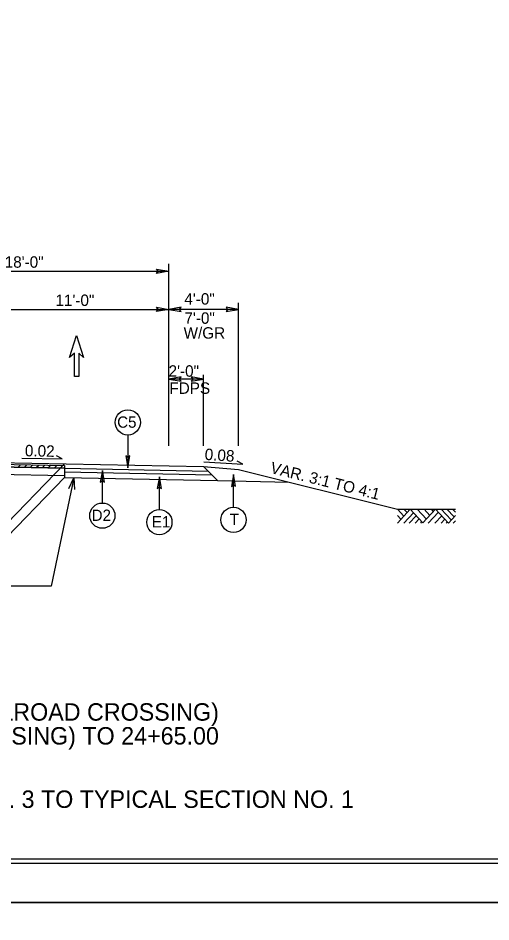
# Model space of a CAD drawing. Extents: x 1901718 to 1902220, y 193828 to 194187.
# Drawn here: x 1902060 to 1902087.2, y 193936.9 to 193988.8 of the extents above; entities that cross this region are included whole.
import ezdxf

# ---------------------------------------------------------------- set-up
doc = ezdxf.new("R2010")
doc.units = 0
for name, color, linetype in [('Old_Level_1', 7, 'Continuous'), ('Old_Level_11', 7, 'Continuous'), ('Old_Level_2', 7, 'Continuous'), ('Old_Level_20', 7, 'Continuous'), ('Prop Dimension', 7, 'Continuous'), ('Prop Dimension Text', 7, 'Continuous'), ('Sheet Border Standard 30in CELL', 7, 'Continuous'), ('Sheet Cutting Line CELL', 7, 'Continuous'), ('Sheet Plot Border Inside CELL', 7, 'Continuous'), ('Sheet Plot Border Outside CELL', 7, 'Continuous'), ('Typical Terminator CELL', 7, 'Continuous')]:
    doc.layers.add(name, color=color, linetype=linetype)

# ---------------------------------------------------------------- blocks, each defined once
blk = doc.blocks.new('TERMINATOR')
at = {"layer": 'Typical Terminator CELL'}
blk.add_lwpolyline([(-0.469, 0.081), (0, 0), (-0.471, -0.083), (-0.411, 0)], close=True, dxfattribs=at)

msp = doc.modelspace()

# ---------------------------------------------------------------- linework, layer by layer
at = {"layer": 'Old_Level_1'}
for p, q in [((1902062.559, 193963.461), (1902062.237, 193963.648)), ((1902050.692, 193963.426), (1902070.692, 193963.026)), ((1902050.692, 193963.322), (1902062.692, 193963.082)), ((1902050.692, 193963.176), (1902062.692, 193962.936)), ((1902062.692, 193962.936), (1902050.692, 193963.176)), ((1902062.692, 193963.186), (1902058.216, 193958.562)), ((1902060.039, 193962.989), (1902060.182, 193963.132)), ((1902060.255, 193963.51), (1902062.559, 193963.461)), ((1902060.386, 193962.982), (1902060.529, 193963.125)), ((1902060.733, 193962.975), (1902060.876, 193963.118)), ((1902061.079, 193962.968), (1902061.222, 193963.112)), ((1902061.426, 193962.961), (1902061.569, 193963.105)), ((1902061.772, 193962.955), (1902061.916, 193963.098)), ((1902062.119, 193962.948), (1902062.262, 193963.091)), ((1902062.466, 193962.941), (1902062.609, 193963.084)), ((1902062.692, 193963.082), (1902062.692, 193962.394)), ((1902070.705, 193963.302), (1902072.94, 193963.156)), ((1902072.94, 193963.156), (1902072.618, 193963.343)), ((1902050.692, 193962.76), (1902062.692, 193962.52)), ((1902062.692, 193962.936), (1902070.948, 193962.771)), ((1902062.692, 193962.728), (1902071.16, 193962.558)), ((1902070.692, 193963.026), (1902072.692, 193962.866)), ((1902070.692, 193963.026), (1902071.5, 193962.218)), ((1902072.692, 193962.866), (1902081.827, 193960.583)), ((1902062.692, 193962.394), (1902058.216, 193957.77)), ((1902062.692, 193962.394), (1902071.5, 193962.218)), ((1902071.5, 193962.218), (1902075.613, 193962.136)), ((1902081.827, 193960.583), (1902082.202, 193960.18)), ((1902081.827, 193959.778), (1902082.569, 193960.575)), ((1902082.202, 193960.583), (1902082.389, 193960.382)), ((1902082.569, 193960.575), (1902083.293, 193959.796)), ((1902082.96, 193960.583), (1902083.493, 193960.01)), ((1902083.293, 193959.796), (1902084.024, 193960.582)), ((1902083.358, 193960.583), (1902083.691, 193960.224)), ((1902083.76, 193960.583), (1902083.893, 193960.44)), ((1902084.024, 193960.582), (1902084.765, 193959.786)), ((1902084.346, 193960.583), (1902084.926, 193959.96)), ((1902084.679, 193960.583), (1902085.093, 193960.139)), ((1902084.999, 193960.583), (1902085.169, 193960.4)), ((1902081.827, 193960.221), (1902082.033, 193959.999)), ((1902082.201, 193959.778), (1902082.755, 193960.374)), ((1902082.51, 193959.778), (1902082.911, 193960.207)), ((1902082.857, 193959.778), (1902083.084, 193960.021)), ((1902083.603, 193959.778), (1902084.189, 193960.406)), ((1902083.973, 193959.778), (1902084.373, 193960.207)), ((1902084.339, 193959.778), (1902084.556, 193960.011)), ((1902084.765, 193959.786), (1902085.169, 193960.221)), ((1902083.168, 193959.778), (1902083.239, 193959.854)), ((1902084.634, 193959.778), (1902084.703, 193959.852)), ((1902085.035, 193959.778), (1902085.169, 193959.921))]:
    msp.add_line(p, q, dxfattribs=at)
for points in [[(1902063.24, 193962.383), (1902061.937, 193956.153), (1902056.546, 193956.153)], [(1902062.947, 193961.774), (1902063.24, 193962.383), (1902063.268, 193961.708)], [(1902081.827, 193960.583), (1902085.169, 193960.583)]]:
    msp.add_lwpolyline(points, dxfattribs=at)
at = {"layer": 'Old_Level_11'}
for p, q in [((1902066.339, 193964.837), (1902066.339, 193962.963)), ((1902064.876, 193960.935), (1902064.876, 193962.81)), ((1902072.411, 193960.691), (1902072.411, 193962.565)), ((1902068.153, 193960.56), (1902068.153, 193962.434))]:
    msp.add_line(p, q, dxfattribs=at)
for points in [[(1902066.224, 193963.634), (1902066.339, 193962.963), (1902066.459, 193963.638), (1902066.339, 193963.552)], [(1902064.991, 193962.138), (1902064.876, 193962.81), (1902064.756, 193962.134), (1902064.876, 193962.22)], [(1902072.527, 193961.894), (1902072.411, 193962.565), (1902072.292, 193961.89), (1902072.411, 193961.976)], [(1902068.269, 193961.763), (1902068.153, 193962.434), (1902068.034, 193961.759), (1902068.153, 193961.845)]]:
    msp.add_lwpolyline(points, close=True, dxfattribs=at)
for centre in [(1902066.339, 193965.562), (1902064.876, 193960.21), (1902068.153, 193959.835), (1902072.411, 193959.966)]:
    msp.add_circle(centre, 0.725, dxfattribs=at)
at = {"layer": 'Prop Dimension'}
for p, q in [((1902068.692, 193964.218), (1902068.692, 193974.669)), ((1902050.692, 193974.24), (1902068.692, 193974.24)), ((1902072.692, 193964.218), (1902072.692, 193972.416)), ((1902057.692, 193972.046), (1902068.692, 193972.046)), ((1902070.692, 193964.218), (1902070.692, 193968.296)), ((1902070.692, 193968.046), (1902068.692, 193968.046))]:
    msp.add_line(p, q, dxfattribs=at)
msp.add_lwpolyline([(1902063.79, 193969.284), (1902063.519, 193969.534), (1902063.519, 193968.201), (1902063.269, 193968.201), (1902063.269, 193969.534), (1902062.998, 193969.284), (1902063.394, 193970.555)], close=True, dxfattribs=at)
msp.add_lwpolyline([(1902063.79, 193969.284), (1902063.519, 193969.534), (1902063.519, 193968.201), (1902063.269, 193968.201), (1902063.269, 193969.534), (1902062.998, 193969.284), (1902063.394, 193970.555)], close=True, dxfattribs=at)
at = {"layer": 'Prop Dimension Text'}
msp.add_line((1902072.692, 193972.046), (1902068.692, 193972.046), dxfattribs=at)
at = {"layer": 'Sheet Border Standard 30in CELL'}
msp.add_lwpolyline([(1902132.544, 194045.514), (1901982.544, 194045.514), (1901982.544, 193940.514), (1902132.544, 193940.514)], close=True, dxfattribs=at)
at = {"layer": 'Sheet Cutting Line CELL'}
for p, q in [((1901965.844, 193938.014), (1902134.244, 193938.014)), ((1902134.244, 193938.014), (1901965.844, 193938.014))]:
    msp.add_line(p, q, dxfattribs=at)
at = {"layer": 'Sheet Plot Border Inside CELL'}
msp.add_lwpolyline([(1902133.794, 194045.769), (1901967.144, 194045.769), (1901967.144, 193940.259), (1902133.794, 193940.259)], close=True, dxfattribs=at)
at = {"layer": 'Sheet Plot Border Outside CELL'}
for points in [[(1902134.244, 194048.014), (1901965.844, 194048.014), (1901965.844, 193938.014), (1902134.244, 193938.014)], [(1902134.244, 193938.014), (1901965.844, 193938.014), (1901965.844, 193828.014), (1902134.244, 193828.014)]]:
    msp.add_lwpolyline(points, close=True, dxfattribs=at)

# ---------------------------------------------------------------- block references
at = {"layer": 'Prop Dimension', "xscale": 1.5}
for p, yscale in [((1902068.692, 193974.24), 1.5), ((1902068.692, 193972.046), 1.5), ((1902072.692, 193972.046), -1.5), ((1902070.692, 193968.046), -1.5)]:
    msp.add_blockref('TERMINATOR', p, dxfattribs=dict(at, yscale=yscale))
at = {"layer": 'Prop Dimension', "xscale": 1.5, "yscale": -1.5, "rotation": -180}
for p in [(1902068.692, 193972.046), (1902068.692, 193968.046)]:
    msp.add_blockref('TERMINATOR', p, dxfattribs=at)

# ---------------------------------------------------------------- texts
at = {"layer": 'Old_Level_1'}
msp.add_text('VAR. 3:1 TO 4:1', height=0.656, rotation=345.9638, dxfattribs=at).set_placement((1902074.483, 193962.668))
at = {"layer": 'Old_Level_11'}
for s, p in [('-L- STA 24+38.00 TO 24+45.98 (RAILROAD CROSSING)', (1902037.162, 193948.443)), ('-L- STA 24+56.06 (RAILROAD CROSSING) TO 24+65.00', (1902037.162, 193947.073)), ('TRANSITION FROM TYPICAL SECTION NO. 3 TO TYPICAL SECTION NO. 1', (1902032.45, 193943.436))]:
    msp.add_text(s, height=1, dxfattribs=at).set_placement(p)
at = {"layer": 'Old_Level_2'}
for s, rotation, p in [('0.02', 358.8084, (1902060.421, 193963.617)), ('0.08', 356.2834, (1902070.741, 193963.411))]:
    msp.add_text(s, height=0.656, rotation=rotation, dxfattribs=at).set_placement(p)
at = {"layer": 'Old_Level_20'}
for s, height, p in [('C5', 0.6491, (1902065.728, 193965.256)), ('D2', 0.6491, (1902064.261, 193959.907)), ('E1', 0.6491, (1902067.72, 193959.531)), ('T', 0.649, (1902072.2, 193959.673))]:
    msp.add_text(s, height=height, dxfattribs=at).set_placement(p)
at = {"layer": 'Prop Dimension'}
for s, p in [('18\'-0" ', (1902059.265, 193974.438)), ('11\'-0" ', (1902062.182, 193972.244)), ('2\'-0"', (1902068.682, 193968.184)), ('FDPS', (1902068.729, 193967.2))]:
    msp.add_text(s, height=0.656, dxfattribs=at).set_placement(p)
at = {"layer": 'Prop Dimension Text'}
for s, p in [('4\'-0"', (1902069.589, 193972.321)), ('7\'-0"', (1902069.593, 193971.221)), ('W/GR', (1902069.546, 193970.368))]:
    msp.add_text(s, height=0.656, dxfattribs=at).set_placement(p)

doc.saveas('drawing.dxf')
